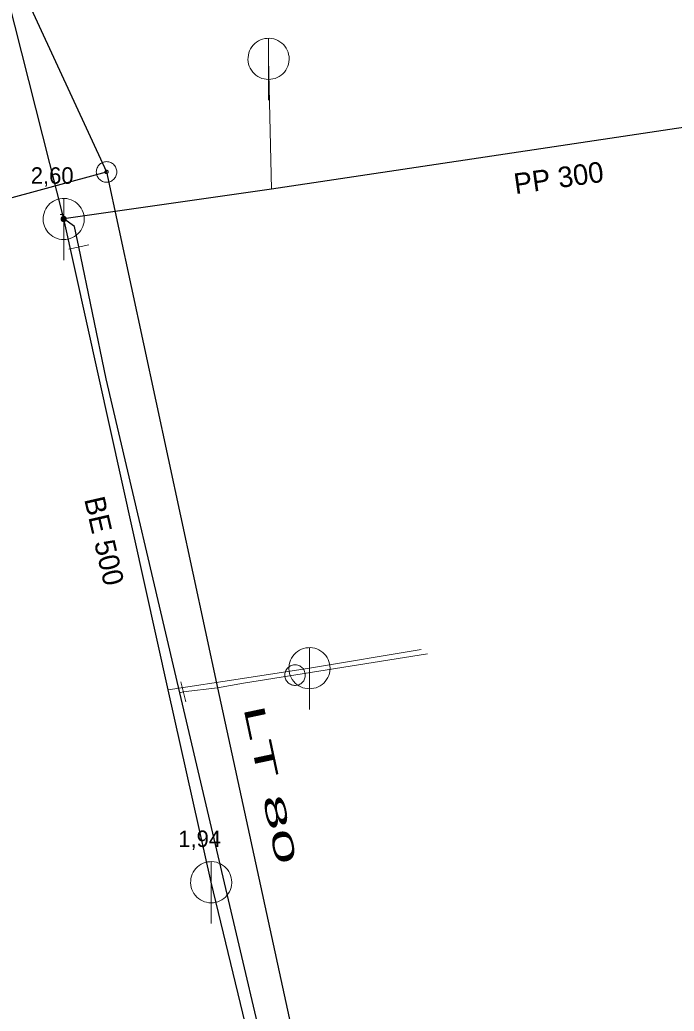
# Model space of a CAD drawing. Extents: x -682839 to -682312, y -994645 to -993949.
# Drawn here: x -682686.28 to -682654.47, y -994218.59 to -994170.41 of the extents above; entities that cross this region are included whole.
import ezdxf

# ---------------------------------------------------------------- set-up
doc = ezdxf.new("R2010")
doc.units = 0
doc.header["$LTSCALE"] = 0.4
doc.layers.add('1', color=7, linetype='Continuous')
for name, color, linetype, lineweight in [('11', 7, 'Continuous', 13), ('13', 7, 'Continuous', 13), ('14', 7, 'Continuous', 25), ('17', 7, 'Continuous', 25), ('22', 7, 'Continuous', 13), ('23', 7, 'Continuous', 13), ('34', 7, 'Continuous', 13), ('47', 7, 'Continuous', 13), ('9', 7, 'Continuous', 13)]:
    doc.layers.add(name, color=color, linetype=linetype, lineweight=lineweight)

msp = doc.modelspace()

# ---------------------------------------------------------------- linework, layer by layer
at = {"layer": '11'}
for p, q in [((-682674.19, -994172.309), (-682674.05, -994178.64)), ((-682666.765, -994201.004), (-682672.199, -994201.92))]:
    msp.add_line(p, q, dxfattribs=at)
msp.add_lwpolyline([(-682672.199, -994201.92), (-682675.452, -994202.416), (-682679.065, -994202.967)], dxfattribs=at)
at = {"layer": '13'}
msp.add_lwpolyline([(-682678.337, -994203.075), (-682676.664, -994202.874), (-682675.405, -994202.646), (-682672.87, -994202.249), (-682666.463, -994201.223)], dxfattribs=at)
at = {"layer": '14'}
for p, q in [((-682684.149, -994180.09), (-682694.03, -994140.85)), ((-682670.965, -994237.204), (-682676.98, -994212.32))]:
    msp.add_line(p, q, dxfattribs=at)
at = {"layer": '14', "lineweight": 13}
msp.add_line((-682678.337, -994203.075), (-682678.495, -994203.114), dxfattribs=at)
at = {"layer": '14'}
for points in [[(-682634.89, -994172.78), (-682652.62, -994175.43), (-682674.05, -994178.64), (-682684.149, -994180.09)], [(-682676.98, -994212.32), (-682679.065, -994202.967), (-682684.149, -994180.09)]]:
    msp.add_lwpolyline(points, dxfattribs=at)
at = {"layer": '17'}
msp.add_line((-682765.462, -994200.262), (-682682.065, -994177.804), dxfattribs=at)
for points in [[(-682710, -994096.699), (-682700.333, -994138.327), (-682682.065, -994177.804)], [(-682682.065, -994177.804), (-682676.664, -994202.874), (-682669.647, -994235.166)], [(-682683.409, -994181.449), (-682683.629, -994180.449), (-682684.149, -994180.09)], [(-682658.389, -994263.379), (-682663.01, -994264.62), (-682663.77, -994264.3), (-682664.26, -994263.37), (-682664.93, -994260.84), (-682678.495, -994203.114), (-682682.079, -994187.859), (-682683.409, -994181.449)]]:
    msp.add_lwpolyline(points, dxfattribs=at)
at = {"layer": '22'}
for p, q in [((-682674.19, -994174.309), (-682674.189, -994171.309)), ((-682684.15, -994182.09), (-682684.149, -994179.09)), ((-682672.199, -994203.92), (-682672.198, -994200.92)), ((-682676.98, -994214.32), (-682676.979, -994211.32))]:
    msp.add_line(p, q, dxfattribs=at)
for points in [[(-682673.19, -994172.309), (-682673.195, -994172.2), (-682673.213, -994172.092), (-682673.243, -994171.986), (-682673.283, -994171.885), (-682673.335, -994171.788), (-682673.397, -994171.698), (-682673.469, -994171.615), (-682673.549, -994171.541), (-682673.637, -994171.475), (-682673.731, -994171.42), (-682673.831, -994171.375), (-682673.936, -994171.342), (-682674.043, -994171.32), (-682674.152, -994171.31), (-682674.262, -994171.312), (-682674.37, -994171.326), (-682674.477, -994171.351), (-682674.58, -994171.388), (-682674.678, -994171.437), (-682674.77, -994171.495), (-682674.856, -994171.564), (-682674.933, -994171.641), (-682675.002, -994171.727), (-682675.061, -994171.819), (-682675.109, -994171.917), (-682675.146, -994172.02), (-682675.172, -994172.127), (-682675.186, -994172.235), (-682675.189, -994172.345), (-682675.179, -994172.454), (-682675.158, -994172.561), (-682675.124, -994172.665), (-682675.08, -994172.765), (-682675.025, -994172.86), (-682674.959, -994172.948), (-682674.885, -994173.028), (-682674.802, -994173.1), (-682674.712, -994173.162), (-682674.616, -994173.214), (-682674.514, -994173.255), (-682674.409, -994173.285), (-682674.301, -994173.303), (-682674.191, -994173.309), (-682674.082, -994173.303), (-682673.974, -994173.285), (-682673.869, -994173.256), (-682673.767, -994173.215), (-682673.67, -994173.163), (-682673.58, -994173.101), (-682673.497, -994173.03), (-682673.422, -994172.95), (-682673.357, -994172.862), (-682673.301, -994172.768), (-682673.257, -994172.668), (-682673.223, -994172.564), (-682673.201, -994172.456), (-682673.191, -994172.347)], [(-682683.15, -994180.09), (-682683.155, -994179.981), (-682683.173, -994179.873), (-682683.203, -994179.767), (-682683.243, -994179.666), (-682683.295, -994179.569), (-682683.357, -994179.479), (-682683.429, -994179.396), (-682683.509, -994179.322), (-682683.597, -994179.256), (-682683.691, -994179.201), (-682683.791, -994179.156), (-682683.896, -994179.123), (-682684.003, -994179.101), (-682684.112, -994179.091), (-682684.222, -994179.093), (-682684.33, -994179.107), (-682684.437, -994179.132), (-682684.54, -994179.169), (-682684.638, -994179.218), (-682684.73, -994179.276), (-682684.816, -994179.345), (-682684.893, -994179.422), (-682684.962, -994179.508), (-682685.021, -994179.6), (-682685.069, -994179.698), (-682685.106, -994179.801), (-682685.132, -994179.908), (-682685.146, -994180.016), (-682685.149, -994180.126), (-682685.139, -994180.235), (-682685.118, -994180.342), (-682685.084, -994180.446), (-682685.04, -994180.546), (-682684.985, -994180.641), (-682684.919, -994180.729), (-682684.845, -994180.809), (-682684.762, -994180.881), (-682684.672, -994180.943), (-682684.576, -994180.995), (-682684.474, -994181.036), (-682684.369, -994181.066), (-682684.261, -994181.084), (-682684.151, -994181.09), (-682684.042, -994181.084), (-682683.934, -994181.066), (-682683.829, -994181.037), (-682683.727, -994180.996), (-682683.63, -994180.944), (-682683.54, -994180.882), (-682683.457, -994180.811), (-682683.382, -994180.731), (-682683.317, -994180.643), (-682683.261, -994180.549), (-682683.217, -994180.449), (-682683.183, -994180.345), (-682683.161, -994180.237), (-682683.151, -994180.128)], [(-682671.199, -994201.92), (-682671.204, -994201.811), (-682671.222, -994201.703), (-682671.252, -994201.597), (-682671.292, -994201.496), (-682671.344, -994201.399), (-682671.406, -994201.309), (-682671.478, -994201.226), (-682671.558, -994201.152), (-682671.646, -994201.086), (-682671.74, -994201.031), (-682671.84, -994200.986), (-682671.945, -994200.953), (-682672.052, -994200.931), (-682672.161, -994200.921), (-682672.271, -994200.923), (-682672.379, -994200.937), (-682672.486, -994200.962), (-682672.589, -994200.999), (-682672.687, -994201.048), (-682672.779, -994201.106), (-682672.865, -994201.175), (-682672.942, -994201.252), (-682673.011, -994201.338), (-682673.07, -994201.43), (-682673.118, -994201.528), (-682673.155, -994201.631), (-682673.181, -994201.738), (-682673.195, -994201.846), (-682673.198, -994201.956), (-682673.188, -994202.065), (-682673.167, -994202.172), (-682673.133, -994202.276), (-682673.089, -994202.376), (-682673.034, -994202.471), (-682672.968, -994202.559), (-682672.894, -994202.639), (-682672.811, -994202.711), (-682672.721, -994202.773), (-682672.625, -994202.825), (-682672.523, -994202.866), (-682672.418, -994202.896), (-682672.31, -994202.914), (-682672.2, -994202.92), (-682672.091, -994202.914), (-682671.983, -994202.896), (-682671.878, -994202.867), (-682671.776, -994202.826), (-682671.679, -994202.774), (-682671.589, -994202.712), (-682671.506, -994202.641), (-682671.431, -994202.561), (-682671.366, -994202.473), (-682671.31, -994202.379), (-682671.266, -994202.279), (-682671.232, -994202.175), (-682671.21, -994202.067), (-682671.2, -994201.958)], [(-682675.98, -994212.32), (-682675.985, -994212.211), (-682676.003, -994212.103), (-682676.033, -994211.997), (-682676.073, -994211.896), (-682676.125, -994211.799), (-682676.187, -994211.709), (-682676.259, -994211.626), (-682676.339, -994211.552), (-682676.427, -994211.486), (-682676.521, -994211.431), (-682676.621, -994211.386), (-682676.726, -994211.353), (-682676.833, -994211.331), (-682676.942, -994211.321), (-682677.052, -994211.323), (-682677.16, -994211.337), (-682677.267, -994211.362), (-682677.37, -994211.399), (-682677.468, -994211.448), (-682677.56, -994211.506), (-682677.646, -994211.575), (-682677.723, -994211.652), (-682677.792, -994211.738), (-682677.851, -994211.83), (-682677.899, -994211.928), (-682677.936, -994212.031), (-682677.962, -994212.138), (-682677.976, -994212.246), (-682677.979, -994212.356), (-682677.969, -994212.465), (-682677.948, -994212.572), (-682677.914, -994212.676), (-682677.87, -994212.776), (-682677.815, -994212.871), (-682677.749, -994212.959), (-682677.675, -994213.039), (-682677.592, -994213.111), (-682677.502, -994213.173), (-682677.406, -994213.225), (-682677.304, -994213.266), (-682677.199, -994213.296), (-682677.091, -994213.314), (-682676.981, -994213.32), (-682676.872, -994213.314), (-682676.764, -994213.296), (-682676.659, -994213.267), (-682676.557, -994213.226), (-682676.46, -994213.174), (-682676.37, -994213.112), (-682676.287, -994213.041), (-682676.212, -994212.961), (-682676.147, -994212.873), (-682676.091, -994212.779), (-682676.047, -994212.679), (-682676.013, -994212.575), (-682675.991, -994212.467), (-682675.981, -994212.358)]]:
    msp.add_lwpolyline(points, close=True, dxfattribs=at)
at = {"layer": '23'}
for points in [[(-682672.482, -994202.527), (-682672.455, -994202.481), (-682672.434, -994202.433), (-682672.419, -994202.384), (-682672.408, -994202.332), (-682672.402, -994202.281), (-682672.403, -994202.228), (-682672.408, -994202.176), (-682672.419, -994202.126), (-682672.435, -994202.075), (-682672.456, -994202.028), (-682672.482, -994201.982), (-682672.514, -994201.939), (-682672.548, -994201.901), (-682672.587, -994201.866), (-682672.629, -994201.835), (-682672.676, -994201.809), (-682672.722, -994201.788), (-682672.774, -994201.771), (-682672.823, -994201.76), (-682672.875, -994201.754), (-682672.929, -994201.756), (-682672.98, -994201.761), (-682673.032, -994201.772), (-682673.082, -994201.788), (-682673.129, -994201.809), (-682673.175, -994201.836), (-682673.216, -994201.867), (-682673.255, -994201.902), (-682673.29, -994201.941), (-682673.321, -994201.983), (-682673.347, -994202.028), (-682673.368, -994202.076), (-682673.385, -994202.126), (-682673.396, -994202.177), (-682673.4, -994202.228), (-682673.4, -994202.281), (-682673.395, -994202.333), (-682673.384, -994202.385), (-682673.368, -994202.435)], [(-682672.774, -994201.771), (-682672.823, -994201.76), (-682672.875, -994201.754), (-682672.929, -994201.756), (-682672.98, -994201.761), (-682673.032, -994201.772), (-682673.082, -994201.788), (-682673.129, -994201.809), (-682673.175, -994201.836), (-682673.216, -994201.867), (-682673.255, -994201.902), (-682673.29, -994201.941), (-682673.321, -994201.983), (-682673.347, -994202.028), (-682673.368, -994202.076), (-682673.385, -994202.126), (-682673.396, -994202.177), (-682673.4, -994202.228), (-682673.4, -994202.281), (-682673.395, -994202.333), (-682673.384, -994202.385), (-682673.368, -994202.435), (-682673.347, -994202.482), (-682673.32, -994202.527), (-682673.29, -994202.57), (-682673.254, -994202.609), (-682673.215, -994202.643), (-682673.174, -994202.674), (-682673.128, -994202.699), (-682673.08, -994202.721), (-682673.03, -994202.738), (-682672.979, -994202.748), (-682672.927, -994202.754), (-682672.875, -994202.754), (-682672.823, -994202.747), (-682672.772, -994202.738), (-682672.722, -994202.721), (-682672.673, -994202.7), (-682672.628, -994202.673), (-682672.586, -994202.643)], [(-682673.368, -994202.435), (-682673.347, -994202.482), (-682673.32, -994202.527), (-682673.29, -994202.57), (-682673.254, -994202.609), (-682673.215, -994202.643), (-682673.174, -994202.674), (-682673.128, -994202.699), (-682673.08, -994202.721), (-682673.03, -994202.738), (-682672.979, -994202.748), (-682672.927, -994202.754), (-682672.875, -994202.754), (-682672.823, -994202.747), (-682672.772, -994202.738), (-682672.722, -994202.721), (-682672.673, -994202.7), (-682672.628, -994202.673), (-682672.586, -994202.643), (-682672.548, -994202.607), (-682672.513, -994202.569), (-682672.482, -994202.527), (-682672.455, -994202.481), (-682672.434, -994202.433), (-682672.419, -994202.384), (-682672.408, -994202.332), (-682672.402, -994202.281), (-682672.403, -994202.228), (-682672.408, -994202.176), (-682672.419, -994202.126), (-682672.435, -994202.075), (-682672.456, -994202.028), (-682672.482, -994201.982), (-682672.514, -994201.939), (-682672.548, -994201.901), (-682672.587, -994201.866), (-682672.629, -994201.835), (-682672.676, -994201.809), (-682672.722, -994201.788), (-682672.774, -994201.771)], [(-682672.586, -994202.643), (-682672.548, -994202.607), (-682672.513, -994202.569), (-682672.482, -994202.527)]]:
    msp.add_lwpolyline(points, dxfattribs=at)
at = {"layer": '34'}
for p, q in [((-682682.919, -994181.346), (-682683.898, -994181.55)), ((-682678.455, -994202.589), (-682678.219, -994203.561))]:
    msp.add_line(p, q, dxfattribs=at)
at = {"layer": '47'}
for points in [[(-682681.565, -994177.804), (-682681.568, -994177.752), (-682681.576, -994177.7), (-682681.59, -994177.65), (-682681.607, -994177.601), (-682681.632, -994177.554), (-682681.661, -994177.51), (-682681.693, -994177.47), (-682681.73, -994177.433), (-682681.771, -994177.4), (-682681.815, -994177.371), (-682681.862, -994177.347), (-682681.911, -994177.329), (-682681.96, -994177.315), (-682682.012, -994177.307), (-682682.065, -994177.304), (-682682.117, -994177.307), (-682682.169, -994177.315), (-682682.22, -994177.329), (-682682.267, -994177.347), (-682682.315, -994177.371), (-682682.358, -994177.4), (-682682.399, -994177.433), (-682682.436, -994177.47), (-682682.47, -994177.51), (-682682.497, -994177.554), (-682682.522, -994177.601), (-682682.541, -994177.65), (-682682.553, -994177.7), (-682682.561, -994177.752), (-682682.565, -994177.804), (-682682.561, -994177.856), (-682682.553, -994177.908), (-682682.541, -994177.959), (-682682.522, -994178.007), (-682682.497, -994178.054), (-682682.47, -994178.098), (-682682.436, -994178.139), (-682682.399, -994178.176), (-682682.358, -994178.209), (-682682.315, -994178.237), (-682682.267, -994178.261), (-682682.22, -994178.28), (-682682.169, -994178.293), (-682682.117, -994178.301), (-682682.065, -994178.304), (-682682.012, -994178.301), (-682681.96, -994178.293), (-682681.911, -994178.28), (-682681.862, -994178.261), (-682681.815, -994178.237), (-682681.771, -994178.209), (-682681.73, -994178.176), (-682681.693, -994178.139), (-682681.661, -994178.098), (-682681.632, -994178.054), (-682681.607, -994178.007), (-682681.59, -994177.959), (-682681.576, -994177.908), (-682681.568, -994177.856)], [(-682681.982, -994177.804), (-682681.982, -994177.795), (-682681.985, -994177.787), (-682681.987, -994177.779), (-682681.99, -994177.771), (-682681.994, -994177.763), (-682681.999, -994177.756), (-682682.004, -994177.749), (-682682.009, -994177.743), (-682682.017, -994177.738), (-682682.024, -994177.733), (-682682.031, -994177.729), (-682682.039, -994177.726), (-682682.048, -994177.724), (-682682.056, -994177.722), (-682682.065, -994177.722), (-682682.073, -994177.722), (-682682.081, -994177.724), (-682682.09, -994177.726), (-682682.098, -994177.729), (-682682.105, -994177.733), (-682682.112, -994177.738), (-682682.12, -994177.743), (-682682.125, -994177.749), (-682682.132, -994177.756), (-682682.136, -994177.763), (-682682.139, -994177.771), (-682682.142, -994177.779), (-682682.144, -994177.787), (-682682.147, -994177.795), (-682682.147, -994177.804), (-682682.147, -994177.813), (-682682.144, -994177.821), (-682682.142, -994177.829), (-682682.139, -994177.837), (-682682.136, -994177.845), (-682682.132, -994177.852), (-682682.125, -994177.859), (-682682.12, -994177.865), (-682682.112, -994177.871), (-682682.105, -994177.875), (-682682.098, -994177.879), (-682682.09, -994177.882), (-682682.081, -994177.884), (-682682.073, -994177.886), (-682682.065, -994177.886), (-682682.056, -994177.886), (-682682.048, -994177.884), (-682682.039, -994177.882), (-682682.031, -994177.879), (-682682.024, -994177.875), (-682682.017, -994177.871), (-682682.009, -994177.865), (-682682.004, -994177.859), (-682681.999, -994177.852), (-682681.994, -994177.845), (-682681.99, -994177.837), (-682681.987, -994177.829), (-682681.985, -994177.821), (-682681.982, -994177.813)]]:
    msp.add_lwpolyline(points, close=True, dxfattribs=at)
at = {"layer": '9'}
for points in [[(-682684.275, -994179.884), (-682684.322, -994179.869), (-682684.279, -994179.853)], [(-682684.149, -994179.963), (-682684.149, -994179.87), (-682684.322, -994179.869)]]:
    msp.add_lwpolyline(points, dxfattribs=at)
for points in [[(-682684.276, -994180.089), (-682684.275, -994180.102), (-682684.273, -994180.115), (-682684.27, -994180.128), (-682684.265, -994180.14), (-682684.259, -994180.152), (-682684.252, -994180.163), (-682684.244, -994180.173), (-682684.234, -994180.183), (-682684.224, -994180.191), (-682684.213, -994180.198), (-682684.201, -994180.204), (-682684.189, -994180.209), (-682684.176, -994180.212), (-682684.163, -994180.214), (-682684.15, -994180.217), (-682684.137, -994180.216), (-682684.124, -994180.214), (-682684.111, -994180.211), (-682684.099, -994180.206), (-682684.087, -994180.2), (-682684.076, -994180.193), (-682684.066, -994180.185), (-682684.056, -994180.175), (-682684.048, -994180.165), (-682684.041, -994180.154), (-682684.035, -994180.142), (-682684.03, -994180.13), (-682684.027, -994180.117), (-682684.025, -994180.104), (-682684.023, -994180.091), (-682684.024, -994180.078), (-682684.026, -994180.065), (-682684.029, -994180.052), (-682684.034, -994180.04), (-682684.04, -994180.028), (-682684.047, -994180.017), (-682684.055, -994180.007), (-682684.065, -994179.997), (-682684.075, -994179.989), (-682684.086, -994179.982), (-682684.098, -994179.976), (-682684.11, -994179.971), (-682684.123, -994179.968), (-682684.136, -994179.966), (-682684.149, -994179.963), (-682684.162, -994179.964), (-682684.175, -994179.966), (-682684.188, -994179.969), (-682684.2, -994179.974), (-682684.212, -994179.98), (-682684.223, -994179.987), (-682684.233, -994179.995), (-682684.243, -994180.005), (-682684.251, -994180.015), (-682684.258, -994180.026), (-682684.264, -994180.038), (-682684.269, -994180.05), (-682684.272, -994180.063), (-682684.274, -994180.076)], [(-682684.256, -994180.089), (-682684.256, -994180.1), (-682684.254, -994180.111), (-682684.251, -994180.122), (-682684.247, -994180.132), (-682684.242, -994180.142), (-682684.236, -994180.151), (-682684.229, -994180.16), (-682684.221, -994180.168), (-682684.212, -994180.175), (-682684.203, -994180.181), (-682684.193, -994180.186), (-682684.183, -994180.19), (-682684.172, -994180.193), (-682684.161, -994180.195), (-682684.15, -994180.196), (-682684.139, -994180.197), (-682684.128, -994180.195), (-682684.117, -994180.192), (-682684.107, -994180.188), (-682684.097, -994180.183), (-682684.088, -994180.177), (-682684.079, -994180.17), (-682684.071, -994180.162), (-682684.064, -994180.153), (-682684.058, -994180.144), (-682684.053, -994180.134), (-682684.049, -994180.124), (-682684.046, -994180.113), (-682684.044, -994180.102), (-682684.043, -994180.091), (-682684.043, -994180.08), (-682684.045, -994180.069), (-682684.048, -994180.058), (-682684.052, -994180.048), (-682684.057, -994180.038), (-682684.063, -994180.029), (-682684.07, -994180.02), (-682684.078, -994180.012), (-682684.087, -994180.005), (-682684.096, -994179.999), (-682684.106, -994179.994), (-682684.116, -994179.99), (-682684.127, -994179.987), (-682684.138, -994179.985), (-682684.149, -994179.983), (-682684.16, -994179.983), (-682684.171, -994179.985), (-682684.182, -994179.988), (-682684.192, -994179.992), (-682684.202, -994179.997), (-682684.211, -994180.003), (-682684.22, -994180.01), (-682684.228, -994180.018), (-682684.235, -994180.027), (-682684.241, -994180.036), (-682684.246, -994180.046), (-682684.25, -994180.056), (-682684.253, -994180.067), (-682684.255, -994180.078)], [(-682684.237, -994180.089), (-682684.236, -994180.098), (-682684.235, -994180.107), (-682684.232, -994180.116), (-682684.229, -994180.124), (-682684.225, -994180.132), (-682684.22, -994180.14), (-682684.214, -994180.147), (-682684.208, -994180.153), (-682684.201, -994180.159), (-682684.193, -994180.164), (-682684.185, -994180.168), (-682684.177, -994180.171), (-682684.168, -994180.174), (-682684.159, -994180.175), (-682684.15, -994180.178), (-682684.141, -994180.177), (-682684.132, -994180.176), (-682684.123, -994180.173), (-682684.115, -994180.17), (-682684.107, -994180.166), (-682684.099, -994180.161), (-682684.092, -994180.155), (-682684.086, -994180.149), (-682684.08, -994180.142), (-682684.075, -994180.134), (-682684.071, -994180.126), (-682684.068, -994180.118), (-682684.065, -994180.109), (-682684.064, -994180.1), (-682684.062, -994180.091), (-682684.063, -994180.082), (-682684.064, -994180.073), (-682684.067, -994180.064), (-682684.07, -994180.056), (-682684.074, -994180.048), (-682684.079, -994180.04), (-682684.085, -994180.033), (-682684.091, -994180.027), (-682684.098, -994180.021), (-682684.106, -994180.016), (-682684.114, -994180.012), (-682684.122, -994180.009), (-682684.131, -994180.006), (-682684.14, -994180.005), (-682684.149, -994180.002), (-682684.158, -994180.003), (-682684.167, -994180.004), (-682684.176, -994180.007), (-682684.184, -994180.01), (-682684.192, -994180.014), (-682684.2, -994180.019), (-682684.207, -994180.025), (-682684.213, -994180.031), (-682684.219, -994180.038), (-682684.224, -994180.046), (-682684.228, -994180.054), (-682684.231, -994180.062), (-682684.234, -994180.071), (-682684.235, -994180.08)], [(-682684.217, -994180.089), (-682684.217, -994180.096), (-682684.215, -994180.103), (-682684.214, -994180.11), (-682684.211, -994180.116), (-682684.208, -994180.122), (-682684.204, -994180.128), (-682684.2, -994180.134), (-682684.195, -994180.139), (-682684.189, -994180.143), (-682684.183, -994180.147), (-682684.177, -994180.15), (-682684.171, -994180.153), (-682684.164, -994180.154), (-682684.157, -994180.156), (-682684.15, -994180.157), (-682684.143, -994180.158), (-682684.136, -994180.156), (-682684.129, -994180.155), (-682684.123, -994180.152), (-682684.116, -994180.149), (-682684.111, -994180.145), (-682684.105, -994180.141), (-682684.1, -994180.136), (-682684.096, -994180.13), (-682684.092, -994180.124), (-682684.089, -994180.118), (-682684.086, -994180.112), (-682684.084, -994180.105), (-682684.083, -994180.098), (-682684.082, -994180.091), (-682684.082, -994180.084), (-682684.083, -994180.077), (-682684.085, -994180.07), (-682684.088, -994180.064), (-682684.091, -994180.057), (-682684.095, -994180.052), (-682684.099, -994180.046), (-682684.104, -994180.041), (-682684.11, -994180.037), (-682684.115, -994180.033), (-682684.122, -994180.03), (-682684.128, -994180.027), (-682684.135, -994180.025), (-682684.142, -994180.024), (-682684.149, -994180.022), (-682684.156, -994180.022), (-682684.163, -994180.023), (-682684.17, -994180.025), (-682684.176, -994180.028), (-682684.182, -994180.031), (-682684.188, -994180.035), (-682684.194, -994180.039), (-682684.199, -994180.044), (-682684.203, -994180.05), (-682684.207, -994180.055), (-682684.21, -994180.062), (-682684.213, -994180.068), (-682684.214, -994180.075), (-682684.216, -994180.082)], [(-682684.197, -994180.089), (-682684.197, -994180.094), (-682684.196, -994180.099), (-682684.195, -994180.104), (-682684.193, -994180.108), (-682684.191, -994180.113), (-682684.188, -994180.117), (-682684.185, -994180.12), (-682684.181, -994180.124), (-682684.178, -994180.127), (-682684.174, -994180.13), (-682684.169, -994180.132), (-682684.165, -994180.134), (-682684.16, -994180.135), (-682684.155, -994180.136), (-682684.15, -994180.137), (-682684.145, -994180.138), (-682684.14, -994180.137), (-682684.135, -994180.136), (-682684.131, -994180.134), (-682684.126, -994180.132), (-682684.122, -994180.129), (-682684.118, -994180.126), (-682684.115, -994180.122), (-682684.112, -994180.119), (-682684.109, -994180.115), (-682684.107, -994180.11), (-682684.105, -994180.106), (-682684.104, -994180.101), (-682684.103, -994180.096), (-682684.102, -994180.091), (-682684.102, -994180.086), (-682684.103, -994180.081), (-682684.104, -994180.076), (-682684.106, -994180.072), (-682684.108, -994180.067), (-682684.111, -994180.063), (-682684.114, -994180.059), (-682684.117, -994180.056), (-682684.121, -994180.053), (-682684.125, -994180.05), (-682684.13, -994180.048), (-682684.134, -994180.046), (-682684.139, -994180.045), (-682684.144, -994180.044), (-682684.149, -994180.043), (-682684.154, -994180.042), (-682684.159, -994180.043), (-682684.164, -994180.044), (-682684.168, -994180.046), (-682684.173, -994180.048), (-682684.177, -994180.051), (-682684.18, -994180.054), (-682684.184, -994180.057), (-682684.187, -994180.061), (-682684.19, -994180.065), (-682684.192, -994180.07), (-682684.194, -994180.074), (-682684.195, -994180.079), (-682684.196, -994180.084)], [(-682684.177, -994180.089), (-682684.177, -994180.092), (-682684.177, -994180.095), (-682684.176, -994180.097), (-682684.175, -994180.1), (-682684.174, -994180.103), (-682684.172, -994180.105), (-682684.17, -994180.107), (-682684.168, -994180.109), (-682684.166, -994180.111), (-682684.164, -994180.113), (-682684.161, -994180.114), (-682684.158, -994180.115), (-682684.156, -994180.116), (-682684.153, -994180.116), (-682684.15, -994180.116), (-682684.147, -994180.118), (-682684.144, -994180.118), (-682684.141, -994180.117), (-682684.139, -994180.116), (-682684.136, -994180.115), (-682684.134, -994180.113), (-682684.131, -994180.111), (-682684.129, -994180.109), (-682684.128, -994180.107), (-682684.126, -994180.105), (-682684.125, -994180.102), (-682684.124, -994180.099), (-682684.123, -994180.097), (-682684.123, -994180.094), (-682684.121, -994180.091), (-682684.122, -994180.088), (-682684.122, -994180.085), (-682684.123, -994180.082), (-682684.124, -994180.08), (-682684.125, -994180.077), (-682684.127, -994180.075), (-682684.128, -994180.072), (-682684.13, -994180.07), (-682684.133, -994180.069), (-682684.135, -994180.067), (-682684.138, -994180.066), (-682684.14, -994180.065), (-682684.143, -994180.064), (-682684.146, -994180.064), (-682684.149, -994180.061), (-682684.152, -994180.062), (-682684.155, -994180.062), (-682684.157, -994180.063), (-682684.16, -994180.064), (-682684.163, -994180.065), (-682684.165, -994180.067), (-682684.167, -994180.068), (-682684.169, -994180.07), (-682684.171, -994180.073), (-682684.173, -994180.075), (-682684.174, -994180.078), (-682684.175, -994180.08), (-682684.176, -994180.083), (-682684.176, -994180.086)], [(-682684.158, -994180.089), (-682684.158, -994180.09), (-682684.158, -994180.091), (-682684.157, -994180.091), (-682684.157, -994180.092), (-682684.157, -994180.093), (-682684.156, -994180.094), (-682684.156, -994180.094), (-682684.155, -994180.095), (-682684.155, -994180.095), (-682684.154, -994180.096), (-682684.153, -994180.096), (-682684.152, -994180.096), (-682684.152, -994180.097), (-682684.151, -994180.097), (-682684.15, -994180.098), (-682684.149, -994180.098), (-682684.148, -994180.099), (-682684.148, -994180.098), (-682684.147, -994180.098), (-682684.146, -994180.098), (-682684.145, -994180.097), (-682684.145, -994180.097), (-682684.144, -994180.096), (-682684.144, -994180.096), (-682684.143, -994180.095), (-682684.143, -994180.094), (-682684.142, -994180.093), (-682684.142, -994180.093), (-682684.142, -994180.092), (-682684.141, -994180.091), (-682684.141, -994180.09), (-682684.141, -994180.089), (-682684.141, -994180.089), (-682684.142, -994180.088), (-682684.142, -994180.087), (-682684.143, -994180.086), (-682684.143, -994180.086), (-682684.144, -994180.085), (-682684.144, -994180.085), (-682684.145, -994180.084), (-682684.146, -994180.084), (-682684.147, -994180.083), (-682684.147, -994180.083), (-682684.148, -994180.083), (-682684.149, -994180.081), (-682684.15, -994180.081), (-682684.151, -994180.081), (-682684.151, -994180.081), (-682684.152, -994180.082), (-682684.153, -994180.082), (-682684.154, -994180.083), (-682684.154, -994180.083), (-682684.155, -994180.084), (-682684.155, -994180.084), (-682684.156, -994180.085), (-682684.156, -994180.086), (-682684.156, -994180.087), (-682684.157, -994180.087), (-682684.157, -994180.088)]]:
    msp.add_lwpolyline(points, close=True, dxfattribs=at)

# ---------------------------------------------------------------- texts
at = {"layer": '1'}
for s, rotation, p in [('PP 300', 8, (-682662.188, -994178.885)), ('BE 500', 283, (-682683.158, -994193.708))]:
    msp.add_text(s, height=1, rotation=rotation, dxfattribs=at).set_placement(p)
for s, p in [('2,60', (-682685.75, -994178.378)), ('1,94', (-682678.58, -994210.608))]:
    msp.add_text(s, height=0.8, dxfattribs=at).set_placement(p)
at = {"layer": '1', "width": 2.3}
msp.add_text('LT 80 ', height=1, rotation=282, dxfattribs=at).set_placement((-682675.421, -994203.832))

doc.saveas('drawing.dxf')
